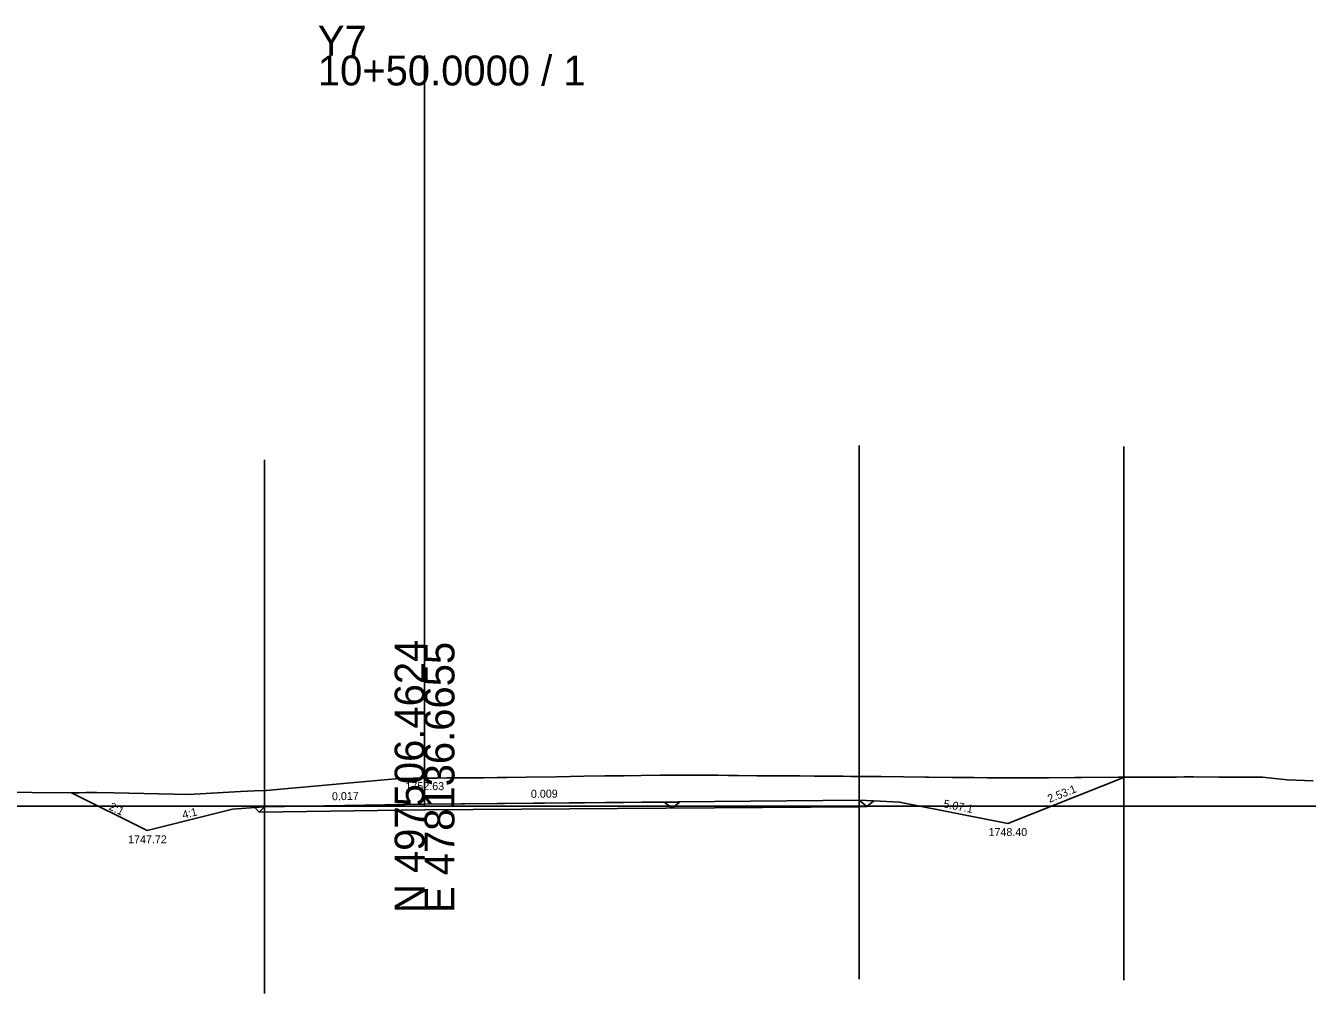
# Model space of a CAD drawing. Extents: x -26 to 403, y -10 to 4071.
# Drawn here: x 162.6 to 282.7, y 482.5 to 573.1 of the extents above; entities that cross this region are included whole.
import ezdxf

# ---------------------------------------------------------------- set-up
doc = ezdxf.new("R2010")
doc.units = 0
for name, color, linetype in [('Exist Cross Section Cell', 7, 'Continuous'), ('Exist XS Center Line Elevation Label', 7, 'Continuous'), ('Exist XS Ground Line', 7, 'Continuous'), ('Prop Road Sect_ Boring - Header (ID Tx)', 7, 'Continuous'), ('Prop XS Ditch Slope Text', 7, 'Continuous'), ('Prop XS Ditch Standard Text', 7, 'Continuous'), ('Prop XS Dump Level', 7, 'Continuous'), ('Prop XS Earthwork Shape', 7, 'Continuous'), ('Prop XS EOT Tick Mark', 7, 'Continuous'), ('Prop XS Finish Grade', 7, 'Continuous'), ('Prop XS Finish Grade Earthwork', 7, 'Continuous'), ('Prop XS Finish Grade Pavement', 7, 'Continuous'), ('Prop XS Pvmt Edge Slope', 7, 'Continuous'), ('Prop XS SE Text', 7, 'Continuous'), ('Prop XS Side Slope Text', 7, 'Continuous'), ('Prop XS Subgrade Earthwork', 7, 'Continuous'), ('Scratch_Level_2', 7, 'Continuous'), ('Scratch_Level_5', 7, 'Continuous')]:
    doc.layers.add(name, color=color, linetype=linetype)

msp = doc.modelspace()

# ---------------------------------------------------------------- linework, layer by layer
at = {"layer": 'Exist Cross Section Cell'}
for p, q in [((200, 500), (200, 570.33)), ((0, 500), (200, 500)), ((200, 500), (400, 500))]:
    msp.add_line(p, q, dxfattribs=at)
at = {"layer": 'Exist XS Ground Line'}
msp.add_lwpolyline([(158.69, 501.32), (167.63, 501.27), (168.3, 501.28), (169.27, 501.3), (170.88, 501.25), (177.89, 501.11), (182.76, 501.38), (184.06, 501.44), (185.16, 501.48), (196.56, 502.52), (197.69, 502.61), (198.96, 502.62), (200, 502.63), (200.44, 502.63), (201.19, 502.64), (202.11, 502.65), (203.29, 502.66), (204.32, 502.66), (205.53, 502.67), (206.81, 502.69), (207.71, 502.7), (209.52, 502.73), (212.35, 502.77), (214.92, 502.81), (216.88, 502.84), (217.61, 502.84), (217.93, 502.85), (218.7, 502.86), (220.29, 502.88), (222.07, 502.91), (222.88, 502.92), (223.43, 502.92), (224.13, 502.92), (225.17, 502.92), (225.73, 502.91), (227.48, 502.9), (228.44, 502.89), (229.4, 502.88), (231.13, 502.86), (231.78, 502.86), (233.24, 502.85), (233.83, 502.85), (235.16, 502.84), (236.54, 502.83), (238.33, 502.81), (239.24, 502.81), (239.91, 502.8), (241.95, 502.79), (242.78, 502.78), (244.87, 502.77), (246.94, 502.74), (247.24, 502.74), (249.47, 502.7), (249.88, 502.7), (250.94, 502.69), (251.47, 502.69), (252.75, 502.68), (253.67, 502.68), (254.62, 502.67), (255.71, 502.68), (258, 502.67), (258.47, 502.67), (260.96, 502.69), (261.6, 502.69), (265.04, 502.72), (267.33, 502.74), (267.97, 502.74), (270.48, 502.74), (271.18, 502.75), (271.69, 502.75), (272.06, 502.75), (274.41, 502.74), (275.59, 502.73), (277.09, 502.73), (278.53, 502.72), (280.85, 502.48), (283.27, 502.38)], dxfattribs=at)
at = {"layer": 'Prop Road Sect_ Boring - Header (ID Tx)'}
for points in [[(185, 499.95), (184.5, 499.46), (184.08, 499.88)], [(223.19, 499.82), (223.85, 500.34), (222.45, 500.4)]]:
    msp.add_lwpolyline(points, close=True, dxfattribs=at)
at = {"layer": 'Prop XS Dump Level'}
for p, q in [((200.04, 500.2), (185, 499.95)), ((222.45, 500.4), (200.04, 500.2))]:
    msp.add_line(p, q, dxfattribs=at)
at = {"layer": 'Prop XS Earthwork Shape'}
msp.add_lwpolyline([(242.11, 500.5), (244.52, 500.4), (254.65, 498.4), (265.6, 502.73), (265.04, 502.72), (261.6, 502.69), (260.96, 502.69), (258.47, 502.67), (258, 502.67), (255.71, 502.68), (254.62, 502.67), (253.67, 502.68), (252.75, 502.68), (251.47, 502.69), (250.94, 502.69), (249.88, 502.7), (249.47, 502.7), (247.24, 502.74), (246.94, 502.74), (244.87, 502.77), (242.78, 502.78), (241.95, 502.79), (239.91, 502.8), (239.24, 502.81), (238.33, 502.81), (236.54, 502.83), (235.16, 502.84), (233.83, 502.85), (233.24, 502.85), (231.78, 502.86), (231.13, 502.86), (229.4, 502.88), (228.44, 502.89), (227.48, 502.9), (225.73, 502.91), (225.17, 502.92), (224.13, 502.92), (223.43, 502.92), (222.88, 502.92), (222.07, 502.91), (220.29, 502.88), (218.7, 502.86), (217.93, 502.85), (217.61, 502.84), (216.88, 502.84), (214.92, 502.81), (212.35, 502.77), (209.52, 502.73), (207.71, 502.7), (206.81, 502.69), (205.53, 502.67), (204.32, 502.66), (203.29, 502.66), (202.11, 502.65), (201.19, 502.64), (200.44, 502.63), (200, 502.63), (198.96, 502.62), (197.69, 502.61), (196.56, 502.52), (185.16, 501.48), (184.06, 501.44), (182.76, 501.38), (177.89, 501.11), (170.88, 501.25), (169.27, 501.3), (168.3, 501.28), (167.63, 501.27), (166.9, 501.27), (174, 497.72), (182, 499.72), (184.08, 499.88), (184.5, 499.46), (200.04, 499.66), (240.72, 499.94), (240.72, 499.97), (241.45, 499.98)], close=True, dxfattribs=at)
at = {"layer": 'Prop XS EOT Tick Mark'}
for p, q in [((185, 499.95), (185, 500.95)), ((240.72, 500.56), (240.72, 501.56))]:
    msp.add_line(p, q, dxfattribs=at)
at = {"layer": 'Prop XS Finish Grade'}
for p, q in [((185, 499.95), (184.08, 499.88)), ((240.72, 500.56), (242.11, 500.5))]:
    msp.add_line(p, q, dxfattribs=at)
at = {"layer": 'Prop XS Finish Grade Earthwork'}
for p, q in [((254.65, 498.4), (265.6, 502.73)), ((174, 497.72), (166.9, 501.27)), ((182, 499.72), (174, 497.72)), ((184.08, 499.88), (182, 499.72)), ((242.11, 500.5), (244.52, 500.4)), ((244.52, 500.4), (254.65, 498.4))]:
    msp.add_line(p, q, dxfattribs=at)
at = {"layer": 'Prop XS Finish Grade Pavement'}
for p, q in [((185, 499.95), (200.04, 500.2)), ((200.04, 500.2), (240.72, 500.56))]:
    msp.add_line(p, q, dxfattribs=at)
at = {"layer": 'Prop XS Pvmt Edge Slope'}
for p, q in [((185, 499.95), (184.5, 499.46)), ((240.72, 500.56), (241.45, 499.98))]:
    msp.add_line(p, q, dxfattribs=at)
at = {"layer": 'Prop XS Subgrade Earthwork'}
for p, q in [((184.5, 499.46), (184.08, 499.88)), ((240.72, 499.94), (200.04, 499.66)), ((240.72, 499.97), (241.45, 499.98)), ((241.45, 499.98), (242.11, 500.5)), ((200.04, 499.66), (184.5, 499.46))]:
    msp.add_line(p, q, dxfattribs=at)
at = {"layer": 'Scratch_Level_2'}
for p, q in [((240.72, 533.8), (240.72, 483.8)), ((265.52, 533.72), (265.52, 483.72)), ((185, 532.47), (185, 482.47)), ((185, 532.47), (185, 482.47))]:
    msp.add_line(p, q, dxfattribs=at)
at = {"layer": 'Scratch_Level_5'}
msp.add_lwpolyline([(158.69, 501.32), (167.63, 501.27), (168.3, 501.28), (169.27, 501.3), (170.88, 501.25), (177.89, 501.11), (182.76, 501.38), (184.06, 501.44), (185.16, 501.48), (196.56, 502.52), (197.69, 502.61), (198.96, 502.62), (200, 502.63), (200.44, 502.63), (201.19, 502.64), (202.11, 502.65), (203.29, 502.66), (204.32, 502.66), (205.53, 502.67), (206.81, 502.69), (207.71, 502.7), (209.52, 502.73), (212.35, 502.77), (214.92, 502.81), (216.88, 502.84), (217.61, 502.84), (217.93, 502.85), (218.7, 502.86), (220.29, 502.88), (222.07, 502.91), (222.88, 502.92), (223.43, 502.92), (224.13, 502.92), (225.17, 502.92), (225.73, 502.91), (227.48, 502.9), (228.44, 502.89), (229.4, 502.88), (231.13, 502.86), (231.78, 502.86), (233.24, 502.85), (233.83, 502.85), (235.16, 502.84), (236.54, 502.83), (238.33, 502.81), (239.24, 502.81), (239.91, 502.8), (241.95, 502.79), (242.78, 502.78), (244.87, 502.77), (246.94, 502.74), (247.24, 502.74), (249.47, 502.7), (249.88, 502.7), (250.94, 502.69), (251.47, 502.69), (252.75, 502.68), (253.67, 502.68), (254.62, 502.67), (255.71, 502.68), (258, 502.67), (258.47, 502.67), (260.96, 502.69), (261.6, 502.69), (265.04, 502.72), (267.33, 502.74), (267.97, 502.74), (270.48, 502.74), (271.18, 502.75), (271.69, 502.75), (272.06, 502.75), (274.41, 502.74), (275.59, 502.73), (277.09, 502.73), (278.53, 502.72), (280.85, 502.48), (283.27, 502.38)], dxfattribs=at)

# ---------------------------------------------------------------- texts
at = {"layer": 'Exist Cross Section Cell'}
for s, p in [('Y7', (190, 570.33)), ('10+50.0000 / 1', (190, 567.53))]:
    msp.add_text(s, height=2.8, dxfattribs=at).set_placement(p)
for s, p in [('N 497506.4624', (200, 490)), ('E 478136.6655', (202.8, 490))]:
    msp.add_text(s, height=2.8, rotation=90, dxfattribs=at).set_placement(p)
at = {"layer": 'Exist XS Center Line Elevation Label'}
msp.add_text('1752.63', height=0.75, dxfattribs=at).set_placement((198.21, 501.51))
at = {"layer": 'Prop XS Ditch Slope Text'}
for s, rotation, p in [('4:1', 14.0362, (177.4, 498.82)), ('5.07:1', 348.8375, (248.58, 499.9))]:
    msp.add_text(s, height=0.75, rotation=rotation, dxfattribs=at).set_placement(p)
at = {"layer": 'Prop XS Ditch Standard Text'}
for s, p in [('1747.72', (172.22, 496.53)), ('1748.40', (252.85, 497.21))]:
    msp.add_text(s, height=0.75, dxfattribs=at).set_placement(p)
at = {"layer": 'Prop XS Dump Level'}
for p in [(182, 499.68), (226.25, 500.21)]:
    msp.add_text('Case1', height=0.04, dxfattribs=at).set_placement(p)
at = {"layer": 'Prop XS SE Text'}
for s, rotation, p in [('0.017', 0.9591, (191.33, 500.56)), ('0.009', 0.4968, (209.97, 500.79))]:
    msp.add_text(s, height=0.75, rotation=rotation, dxfattribs=at).set_placement(p)
at = {"layer": 'Prop XS Side Slope Text'}
for s, rotation, p in [('2.53:1', 21.5368, (258.56, 500.32)), ('2:1', 333.4349, (170.36, 499.74))]:
    msp.add_text(s, height=0.75, rotation=rotation, dxfattribs=at).set_placement(p)

doc.saveas('drawing.dxf')
